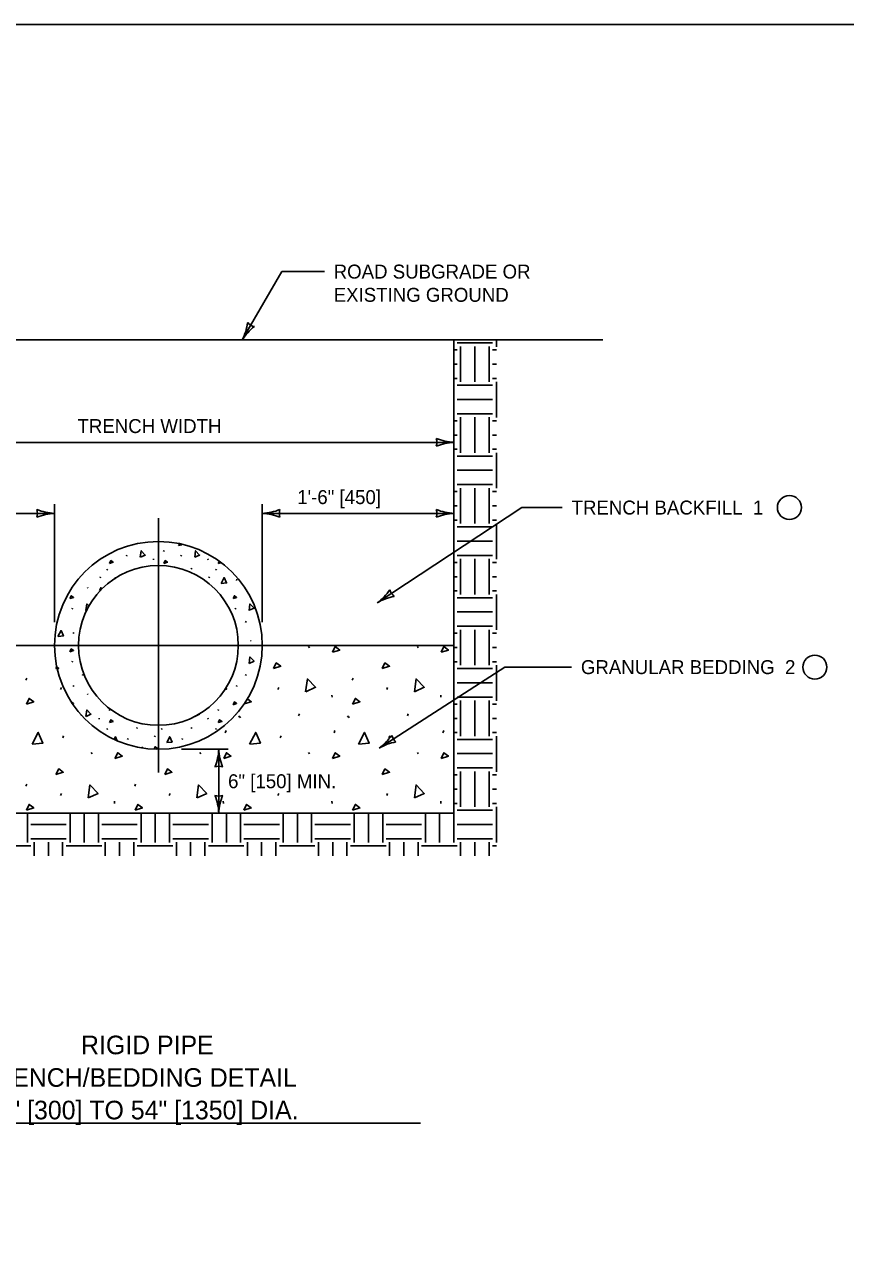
# Model space of a CAD drawing. Extents: x 49991.4 to 50061.4, y 49960.6 to 50011.4.
# Drawn here: x 50001.82 to 50005.35, y 49993.73 to 49999 of the extents above; entities that cross this region are included whole.
import ezdxf

# ---------------------------------------------------------------- set-up
doc = ezdxf.new("R2010")
doc.units = 0
for name, color, linetype in [('Level 1', 7, 'Continuous'), ('Level 2', 7, 'Continuous'), ('Level 3', 7, 'Continuous'), ('Level 5', 7, 'Continuous')]:
    doc.layers.add(name, color=color, linetype=linetype)

msp = doc.modelspace()

# ---------------------------------------------------------------- linework, layer by layer
at = {"layer": 'Level 1'}
for p, q in [((50004.3049, 49997.6424), (50000.4816, 49997.6424)), ((50003.6648, 49997.6424), (50003.6648, 49995.6066)), ((50003.8476, 49997.6424), (50003.8476, 49997.6133)), ((50003.6648, 49997.5991), (50003.6783, 49997.5991)), ((50003.6783, 49997.6297), (50003.8311, 49997.6297)), ((50003.6935, 49997.6144), (50003.6935, 49997.4615)), ((50003.7547, 49997.6144), (50003.7547, 49997.4615)), ((50003.8158, 49997.6144), (50003.8158, 49997.4615)), ((50003.8311, 49997.5991), (50003.8481, 49997.5991)), ((50003.6648, 49997.538), (50003.6783, 49997.538)), ((50003.8311, 49997.538), (50003.8481, 49997.538)), ((50003.6648, 49997.4768), (50003.6783, 49997.4768)), ((50003.6783, 49997.4473), (50003.8311, 49997.4473)), ((50003.8311, 49997.4768), (50003.8481, 49997.4768)), ((50003.8476, 49997.4615), (50003.8476, 49997.3086)), ((50003.6783, 49997.3862), (50003.8311, 49997.3862)), ((50003.6783, 49997.325), (50003.8311, 49997.325)), ((50003.6648, 49997.2944), (50003.6783, 49997.2944)), ((50003.6935, 49997.3097), (50003.6935, 49997.1568)), ((50003.7547, 49997.3097), (50003.7547, 49997.1568)), ((50003.8158, 49997.3097), (50003.8158, 49997.1568)), ((50003.8311, 49997.2944), (50003.8481, 49997.2944)), ((50003.6648, 49997.2333), (50003.6783, 49997.2333)), ((50003.8311, 49997.2333), (50003.8481, 49997.2333)), ((50003.6648, 49997.1721), (50003.6783, 49997.1721)), ((50003.8311, 49997.1721), (50003.8481, 49997.1721)), ((50003.6783, 49997.1426), (50003.8311, 49997.1426)), ((50003.8476, 49997.1568), (50003.8476, 49997.004)), ((50003.6783, 49997.0815), (50003.8311, 49997.0815)), ((50003.6783, 49997.0203), (50003.8311, 49997.0203)), ((50003.6935, 49997.005), (50003.6935, 49996.8521)), ((50003.7547, 49997.005), (50003.7547, 49996.8521)), ((50003.8158, 49997.005), (50003.8158, 49996.8521)), ((50003.6648, 49996.9897), (50003.6783, 49996.9897)), ((50003.8311, 49996.9897), (50003.8481, 49996.9897)), ((50003.6648, 49996.9286), (50003.6783, 49996.9286)), ((50003.8311, 49996.9286), (50003.8481, 49996.9286)), ((50003.6648, 49996.8674), (50003.6783, 49996.8674)), ((50003.8311, 49996.8674), (50003.8481, 49996.8674)), ((50003.8476, 49996.8521), (50003.8476, 49996.6993)), ((50003.6783, 49996.8379), (50003.8311, 49996.8379)), ((50003.6783, 49996.7768), (50003.8311, 49996.7768)), ((50002.256, 49996.7123), (50002.2579, 49996.7167)), ((50002.3721, 49996.7001), (50002.3726, 49996.6957)), ((50002.4157, 49996.7324), (50002.4177, 49996.7368)), ((50002.49, 49996.7123), (50002.4919, 49996.7167)), ((50002.6061, 49996.7001), (50002.6066, 49996.6957)), ((50003.6783, 49996.7156), (50003.8311, 49996.7156)), ((50003.6935, 49996.7003), (50003.6935, 49996.5474)), ((50003.7547, 49996.7003), (50003.7547, 49996.5474)), ((50003.8158, 49996.7003), (50003.8158, 49996.5474)), ((50002.1715, 49996.6557), (50002.1734, 49996.6528)), ((50002.1734, 49996.6546), (50002.1754, 49996.6516)), ((50002.3018, 49996.6588), (50002.3024, 49996.6601)), ((50002.5344, 49996.6557), (50002.5364, 49996.6601)), ((50002.6394, 49996.6557), (50002.6414, 49996.6528)), ((50002.6414, 49996.6546), (50002.6433, 49996.6516)), ((50003.6648, 49996.685), (50003.6783, 49996.685)), ((50003.8311, 49996.685), (50003.8481, 49996.685)), ((50002.1427, 49996.6195), (50002.1446, 49996.6239)), ((50002.6106, 49996.6195), (50002.6125, 49996.6239)), ((50002.7288, 49996.6082), (50002.7307, 49996.6126)), ((50003.6648, 49996.6239), (50003.6783, 49996.6239)), ((50003.8311, 49996.6239), (50003.8481, 49996.6239)), ((50002.088, 49996.577), (50002.0899, 49996.5741)), ((50003.6648, 49996.5627), (50003.6783, 49996.5627)), ((50003.6783, 49996.5332), (50003.8311, 49996.5332)), ((50003.8311, 49996.5627), (50003.8481, 49996.5627)), ((50003.8476, 49996.5474), (50003.8476, 49996.3946)), ((50002.022, 49996.4842), (50002.024, 49996.4886)), ((50002.7239, 49996.4842), (50002.7259, 49996.4886)), ((50002.7684, 49996.4275), (50002.7703, 49996.4319)), ((50003.6783, 49996.4721), (50003.8311, 49996.4721)), ((50002.0269, 49996.3801), (50002.0289, 49996.3845)), ((50002.7305, 49996.3839), (50002.7307, 49996.3845)), ((50003.6648, 49996.3803), (50003.6783, 49996.3803)), ((50003.6783, 49996.4109), (50003.8311, 49996.4109)), ((50003.6935, 49996.3956), (50003.6935, 49996.2427)), ((50003.7547, 49996.3956), (50003.7547, 49996.2427)), ((50003.8158, 49996.3956), (50003.8158, 49996.2427)), ((50003.8311, 49996.3803), (50003.8481, 49996.3803)), ((50001.1217, 49996.3285), (50001.9464, 49996.3285)), ((50002.7898, 49996.3488), (50002.7918, 49996.3459)), ((50002.8401, 49996.3285), (50003.6648, 49996.3285)), ((50003.0395, 49996.3242), (50003.0434, 49996.3183)), ((50003.5074, 49996.3242), (50003.5113, 49996.3183)), ((50003.6648, 49996.3285), (50003.6648, 49995.6066)), ((50003.6648, 49996.3192), (50003.6783, 49996.3192)), ((50003.8311, 49996.3192), (50003.8481, 49996.3192)), ((50001.9525, 49996.2289), (50001.9561, 49996.2364)), ((50001.9573, 49996.2304), (50001.9525, 49996.2289)), ((50002.022, 49996.256), (50002.024, 49996.2604)), ((50003.6648, 49996.258), (50003.6783, 49996.258)), ((50003.6783, 49996.2285), (50003.8311, 49996.2285)), ((50003.8311, 49996.258), (50003.8481, 49996.258)), ((50003.8476, 49996.2427), (50003.8476, 49996.0899)), ((50001.8233, 49996.1786), (50001.8273, 49996.1874)), ((50002.0665, 49996.1994), (50002.0684, 49996.2038)), ((50002.7684, 49996.1994), (50002.7703, 49996.2038)), ((50003.2271, 49996.1786), (50003.231, 49996.1874)), ((50003.6783, 49996.1674), (50003.8311, 49996.1674)), ((50001.9718, 49996.1386), (50001.9757, 49996.1473)), ((50002.0269, 49996.1519), (50002.0289, 49996.1563)), ((50002.088, 49996.1207), (50002.0899, 49996.1178)), ((50002.7288, 49996.1519), (50002.7307, 49996.1563)), ((50002.9077, 49996.1386), (50002.9116, 49996.1473)), ((50003.1399, 49996.114), (50003.1409, 49996.1052)), ((50003.3756, 49996.1386), (50003.3795, 49996.1473)), ((50003.6078, 49996.114), (50003.6088, 49996.1052)), ((50003.6648, 49996.0756), (50003.6783, 49996.0756)), ((50003.6783, 49996.1062), (50003.8311, 49996.1062)), ((50003.6935, 49996.0909), (50003.6935, 49995.9381)), ((50003.7547, 49996.0909), (50003.7547, 49995.9381)), ((50003.8158, 49996.0909), (50003.8158, 49995.9381)), ((50003.8311, 49996.0756), (50003.8481, 49996.0756)), ((50002.0607, 49996.0252), (50002.0622, 49996.0285)), ((50002.1382, 49996.0156), (50002.1386, 49996.0112)), ((50002.1818, 49996.0479), (50002.1837, 49996.0523)), ((50002.6061, 49996.0156), (50002.6066, 49996.0112)), ((50002.6497, 49996.0479), (50002.6516, 49996.0523)), ((50002.7251, 49996.0306), (50002.7259, 49996.0323)), ((50002.7387, 49996.0252), (50002.7426, 49996.0194)), ((50002.7426, 49996.023), (50002.7465, 49996.0172)), ((50002.9965, 49996.0252), (50003.0005, 49996.034)), ((50003.2066, 49996.0252), (50003.2105, 49996.0194)), ((50003.2105, 49996.023), (50003.2144, 49996.0172)), ((50003.4645, 49996.0252), (50003.4684, 49996.034)), ((50003.6648, 49996.0145), (50003.6783, 49996.0145)), ((50003.8311, 49996.0145), (50003.8481, 49996.0145)), ((50002.1715, 49995.9712), (50002.1734, 49995.9683)), ((50002.1734, 49995.9701), (50002.1754, 49995.9672)), ((50002.3004, 49995.9712), (50002.3024, 49995.9756)), ((50002.4055, 49995.9712), (50002.4074, 49995.9683)), ((50002.4074, 49995.9701), (50002.4094, 49995.9672)), ((50002.5344, 49995.9712), (50002.5364, 49995.9756)), ((50002.6394, 49995.9712), (50002.6414, 49995.9683)), ((50002.6414, 49995.9701), (50002.6433, 49995.9672)), ((50002.681, 49995.9528), (50002.6849, 49995.9616)), ((50003.1489, 49995.9528), (50003.1528, 49995.9616)), ((50003.6168, 49995.9528), (50003.6207, 49995.9616)), ((50003.6648, 49995.9533), (50003.6783, 49995.9533)), ((50003.8311, 49995.9533), (50003.8481, 49995.9533)), ((50001.9816, 49995.9304), (50001.9855, 49995.9392)), ((50002.2609, 49995.9238), (50002.2628, 49995.9282)), ((50002.3766, 49995.935), (50002.3786, 49995.9394)), ((50002.4948, 49995.9238), (50002.4968, 49995.9282)), ((50002.9174, 49995.9304), (50002.9213, 49995.9392)), ((50003.3853, 49995.9304), (50003.3892, 49995.9392)), ((50003.6783, 49995.9238), (50003.8311, 49995.9238)), ((50003.8476, 49995.9381), (50003.8476, 49995.7852)), ((50002.1037, 49995.8679), (50002.1076, 49995.862)), ((50002.3219, 49995.8925), (50002.3239, 49995.8896)), ((50002.5716, 49995.8679), (50002.5755, 49995.862)), ((50003.0395, 49995.8679), (50003.0434, 49995.862)), ((50003.5074, 49995.8679), (50003.5113, 49995.862)), ((50003.6783, 49995.8627), (50003.8311, 49995.8627)), ((50003.6783, 49995.8015), (50003.8311, 49995.8015)), ((50003.6648, 49995.771), (50003.6783, 49995.771)), ((50003.6935, 49995.7862), (50003.6935, 49995.6334)), ((50003.7547, 49995.7862), (50003.7547, 49995.6334)), ((50003.8158, 49995.7862), (50003.8158, 49995.6334)), ((50003.8311, 49995.771), (50003.8481, 49995.771)), ((50001.8233, 49995.7223), (50001.8273, 49995.7311)), ((50001.9718, 49995.6823), (50001.9757, 49995.6911)), ((50002.2913, 49995.7223), (50002.2952, 49995.7311)), ((50002.4397, 49995.6823), (50002.4436, 49995.6911)), ((50002.9077, 49995.6823), (50002.9116, 49995.6911)), ((50003.3756, 49995.6823), (50003.3795, 49995.6911)), ((50003.6648, 49995.7098), (50003.6783, 49995.7098)), ((50003.8311, 49995.7098), (50003.8481, 49995.7098)), ((50002.2041, 49995.6577), (50002.205, 49995.6489)), ((50002.672, 49995.6577), (50002.673, 49995.6489)), ((50003.1399, 49995.6577), (50003.1409, 49995.6489)), ((50003.6078, 49995.6577), (50003.6088, 49995.6489)), ((50003.6648, 49995.6486), (50003.6783, 49995.6486)), ((50003.8311, 49995.6486), (50003.8481, 49995.6486)), ((50003.6648, 49995.6066), (50001.1217, 49995.6066)), ((50001.1217, 49995.6066), (50003.6648, 49995.6066)), ((50001.8295, 49995.6066), (50001.8295, 49995.4805)), ((50002.013, 49995.6066), (50002.013, 49995.4805)), ((50002.0741, 49995.6066), (50002.0741, 49995.4805)), ((50002.1353, 49995.6066), (50002.1353, 49995.4805)), ((50002.3187, 49995.6066), (50002.3187, 49995.4805)), ((50002.3799, 49995.6066), (50002.3799, 49995.4805)), ((50002.441, 49995.6066), (50002.441, 49995.4805)), ((50002.6245, 49995.6066), (50002.6245, 49995.4805)), ((50002.6856, 49995.6066), (50002.6856, 49995.4805)), ((50002.7468, 49995.6066), (50002.7468, 49995.4805)), ((50002.9303, 49995.6066), (50002.9303, 49995.4805)), ((50002.9914, 49995.6066), (50002.9914, 49995.4805)), ((50003.0526, 49995.6066), (50003.0526, 49995.4805)), ((50003.236, 49995.6066), (50003.236, 49995.4805)), ((50003.2972, 49995.6066), (50003.2972, 49995.4805)), ((50003.3583, 49995.6066), (50003.3583, 49995.4805)), ((50003.5418, 49995.6066), (50003.5418, 49995.4805)), ((50003.6029, 49995.6066), (50003.6029, 49995.4805)), ((50003.6641, 49995.6066), (50003.6641, 49995.4805)), ((50003.6783, 49995.6191), (50003.8311, 49995.6191)), ((50003.8476, 49995.6334), (50003.8476, 49995.4805)), ((50001.8437, 49995.558), (50001.9965, 49995.558)), ((50002.1494, 49995.558), (50002.3023, 49995.558)), ((50002.4552, 49995.558), (50002.6081, 49995.558)), ((50002.761, 49995.558), (50002.9138, 49995.558)), ((50003.0667, 49995.558), (50003.2196, 49995.558)), ((50003.3725, 49995.558), (50003.5254, 49995.558)), ((50003.6783, 49995.558), (50003.8311, 49995.558)), ((50001.8437, 49995.4968), (50001.9965, 49995.4968)), ((50001.8589, 49995.4815), (50001.8589, 49995.4232)), ((50001.9201, 49995.4815), (50001.9201, 49995.4232)), ((50001.9812, 49995.4815), (50001.9812, 49995.4232)), ((50002.1494, 49995.4968), (50002.3023, 49995.4968)), ((50002.1647, 49995.4815), (50002.1647, 49995.4232)), ((50002.2259, 49995.4815), (50002.2259, 49995.4232)), ((50002.287, 49995.4815), (50002.287, 49995.4232)), ((50002.4552, 49995.4968), (50002.6081, 49995.4968)), ((50002.4705, 49995.4815), (50002.4705, 49995.4232)), ((50002.5316, 49995.4815), (50002.5316, 49995.4232)), ((50002.5928, 49995.4815), (50002.5928, 49995.4232)), ((50002.761, 49995.4968), (50002.9138, 49995.4968)), ((50002.7762, 49995.4815), (50002.7762, 49995.4232)), ((50002.8374, 49995.4815), (50002.8374, 49995.4232)), ((50002.8985, 49995.4815), (50002.8985, 49995.4232)), ((50003.0667, 49995.4968), (50003.2196, 49995.4968)), ((50003.082, 49995.4815), (50003.082, 49995.4232)), ((50003.1432, 49995.4815), (50003.1432, 49995.4232)), ((50003.2043, 49995.4815), (50003.2043, 49995.4232)), ((50003.3725, 49995.4968), (50003.5254, 49995.4968)), ((50003.3878, 49995.4815), (50003.3878, 49995.4232)), ((50003.4489, 49995.4815), (50003.4489, 49995.4232)), ((50003.5101, 49995.4815), (50003.5101, 49995.4232)), ((50003.6783, 49995.4968), (50003.8311, 49995.4968)), ((50003.6935, 49995.4815), (50003.6935, 49995.4232)), ((50003.7547, 49995.4815), (50003.7547, 49995.4232)), ((50003.8158, 49995.4815), (50003.8158, 49995.4232)), ((50001.6908, 49995.4663), (50001.8437, 49995.4663)), ((50001.9965, 49995.4663), (50002.1494, 49995.4663)), ((50002.3023, 49995.4663), (50002.4552, 49995.4663)), ((50002.6081, 49995.4663), (50002.761, 49995.4663)), ((50002.9138, 49995.4663), (50003.0667, 49995.4663)), ((50003.2196, 49995.4663), (50003.3725, 49995.4663)), ((50003.5254, 49995.4663), (50003.6783, 49995.4663)), ((50003.8311, 49995.4663), (50003.8481, 49995.4663))]:
    msp.add_line(p, q, dxfattribs=at)
msp.add_lwpolyline([(49999.3835, 49998.9992), (50016.7501, 49998.9992), (50016.7501, 49987.7988), (49999.3835, 49987.7988)], close=True, dxfattribs=at)
for points in [[(50002.4803, 49996.7575), (50002.4834, 49996.7641)], [(50002.4934, 49996.7616), (50002.4803, 49996.7575)], [(50002.1827, 49996.6811), (50002.1886, 49996.6933), (50002.1984, 49996.686), (50002.1827, 49996.6811)], [(50002.3154, 49996.7073), (50002.3193, 49996.7352), (50002.3368, 49996.7171), (50002.3159, 49996.7074)], [(50002.4167, 49996.6811), (50002.4226, 49996.6933), (50002.4323, 49996.686), (50002.4167, 49996.6811)], [(50002.5494, 49996.7073), (50002.5532, 49996.7352), (50002.5707, 49996.7171), (50002.5498, 49996.7074)], [(50002.6506, 49996.6811), (50002.6542, 49996.6885)], [(50002.6601, 49996.684), (50002.6506, 49996.6811)], [(50002.2051, 49996.6142), (50002.2081, 49996.62), (50002.2093, 49996.6174)], [(50002.6629, 49996.5951), (50002.676, 49996.62), (50002.6863, 49996.597), (50002.6633, 49996.5951)], [(50002.0124, 49996.5294), (50002.0182, 49996.5416), (50002.028, 49996.5343), (50002.0124, 49996.5294)], [(50002.1393, 49996.5643), (50002.1451, 49996.5765), (50002.1514, 49996.5718)], [(50002.1473, 49996.5668), (50002.1393, 49996.5643)], [(50002.7142, 49996.5294), (50002.7201, 49996.5416), (50002.7299, 49996.5343), (50002.7142, 49996.5294)], [(50002.0815, 49996.4791), (50002.0853, 49996.507), (50002.0955, 49996.4966)], [(50002.0884, 49996.4823), (50002.0819, 49996.4793)], [(50002.7833, 49996.4791), (50002.7872, 49996.507), (50002.8047, 49996.489), (50002.7838, 49996.4793)], [(50001.961, 49996.3669), (50001.9742, 49996.3918), (50001.9844, 49996.3689), (50001.9615, 49996.3669)], [(50003.1421, 49996.2988), (50003.1538, 49996.3232), (50003.1733, 49996.3085), (50003.1421, 49996.2988)], [(50003.61, 49996.2988), (50003.6217, 49996.3232), (50003.6413, 49996.3085), (50003.61, 49996.2988)], [(50002.0124, 49996.3012), (50002.0182, 49996.3134), (50002.028, 49996.3061), (50002.0124, 49996.3012)], [(50002.7833, 49996.251), (50002.7872, 49996.2789), (50002.8047, 49996.2608), (50002.7838, 49996.2512)], [(50001.9588, 49996.2339), (50001.9644, 49996.2297), (50001.9601, 49996.2283)], [(50002.8883, 49996.2289), (50002.9, 49996.2533), (50002.9196, 49996.2387), (50002.8883, 49996.2289)], [(50003.3562, 49996.2289), (50003.3679, 49996.2533), (50003.3875, 49996.2387), (50003.3562, 49996.2289)], [(50003.0265, 49996.1284), (50003.0342, 49996.1843), (50003.0692, 49996.1482), (50003.0274, 49996.1288)], [(50003.4944, 49996.1284), (50003.5021, 49996.1843), (50003.5371, 49996.1482), (50003.4953, 49996.1288)], [(50002.6831, 49996.148), (50002.6863, 49996.1407), (50002.678, 49996.14)], [(50001.8253, 49996.076), (50001.837, 49996.1005), (50001.8566, 49996.0858), (50001.8253, 49996.076)], [(50002.0219, 49996.0825), (50002.028, 49996.078), (50002.0259, 49996.0773)], [(50002.7142, 49996.0731), (50002.7201, 49996.0853), (50002.7299, 49996.078), (50002.7142, 49996.0731)], [(50002.776, 49996.0981), (50002.7924, 49996.0858), (50002.7622, 49996.0764)], [(50003.229, 49996.076), (50003.2408, 49996.1005), (50003.2603, 49996.0858), (50003.229, 49996.076)], [(50002.0815, 49996.0228), (50002.0853, 49996.0508), (50002.1028, 49996.0327), (50002.0819, 49996.023)], [(50002.1827, 49995.9966), (50002.1886, 49996.0088), (50002.1984, 49996.0015), (50002.1827, 49995.9966)], [(50002.5494, 49996.0228), (50002.5495, 49996.0241)], [(50002.5682, 49996.0353), (50002.5707, 49996.0327), (50002.5498, 49996.023)], [(50002.6506, 49995.9966), (50002.6565, 49996.0088), (50002.6663, 49996.0015), (50002.6506, 49995.9966)], [(50001.8497, 49995.904), (50001.8761, 49995.9538), (50001.8966, 49995.9079), (50001.8507, 49995.904)], [(50002.7856, 49995.904), (50002.8119, 49995.9538), (50002.8324, 49995.9079), (50002.7865, 49995.904)], [(50003.2535, 49995.904), (50003.2798, 49995.9538), (50003.3004, 49995.9079), (50003.2544, 49995.904)], [(50002.2028, 49995.9254), (50002.2081, 49995.9355), (50002.2157, 49995.9185)], [(50002.4289, 49995.9106), (50002.4421, 49995.9355), (50002.4523, 49995.9126), (50002.4294, 49995.9106)], [(50002.2063, 49995.8425), (50002.218, 49995.8669), (50002.2375, 49995.8522), (50002.2063, 49995.8425)], [(50002.3749, 49995.8834), (50002.3791, 49995.8921), (50002.3888, 49995.8847), (50002.382, 49995.8826)], [(50002.6742, 49995.8425), (50002.6859, 49995.8669), (50002.7054, 49995.8522), (50002.6742, 49995.8425)], [(50003.1421, 49995.8425), (50003.1538, 49995.8669), (50003.1733, 49995.8522), (50003.1421, 49995.8425)], [(50003.61, 49995.8425), (50003.6217, 49995.8669), (50003.6413, 49995.8522), (50003.61, 49995.8425)], [(50001.9525, 49995.7726), (50001.9642, 49995.7971), (50001.9837, 49995.7824), (50001.9525, 49995.7726)], [(50002.4204, 49995.7726), (50002.4321, 49995.7971), (50002.4517, 49995.7824), (50002.4204, 49995.7726)], [(50003.3562, 49995.7726), (50003.3679, 49995.7971), (50003.3875, 49995.7824), (50003.3562, 49995.7726)], [(50002.0907, 49995.6722), (50002.0984, 49995.728), (50002.1334, 49995.6919), (50002.0916, 49995.6725)], [(50002.5586, 49995.6722), (50002.5663, 49995.728), (50002.6013, 49995.6919), (50002.5595, 49995.6725)], [(50003.4944, 49995.6722), (50003.5021, 49995.728), (50003.5371, 49995.6919), (50003.4953, 49995.6725)], [(50001.8253, 49995.6197), (50001.837, 49995.6442), (50001.8566, 49995.6295), (50001.8253, 49995.6197)], [(50002.2932, 49995.6197), (50002.3049, 49995.6442), (50002.3245, 49995.6295), (50002.2932, 49995.6197)], [(50002.7611, 49995.6197), (50002.7729, 49995.6442), (50002.7924, 49995.6295), (50002.7611, 49995.6197)], [(50003.229, 49995.6197), (50003.2408, 49995.6442), (50003.2603, 49995.6295), (50003.229, 49995.6197)]]:
    msp.add_lwpolyline(points, dxfattribs=at)
for radius in [0.4469, 0.3438]:
    msp.add_circle((50002.3932, 49996.3285), radius, dxfattribs=at)
msp.add_arc((50002.3932, 49996.3285), 0.4469, 180, 0, dxfattribs=at)
at = {"layer": 'Level 2'}
msp.add_line((50001.283, 49994.2737), (50003.5203, 49994.2737), dxfattribs=at)
for centre in [(50005.108, 49996.9213), (50005.2176, 49996.2349)]:
    msp.add_circle(centre, 0.0517, dxfattribs=at)
at = {"layer": 'Level 3'}
for p, q in [((50002.7537, 49997.6424), (50002.9239, 49997.9363)), ((50003.1072, 49997.9363), (50002.9239, 49997.9363)), ((50001.1217, 49997.2018), (50003.6648, 49997.2018)), ((50001.9464, 49996.4285), (50001.9464, 49996.9362)), ((50002.8401, 49996.4285), (50002.8401, 49996.9362)), ((50003.3347, 49996.5116), (50003.9573, 49996.9213)), ((50004.1309, 49996.9213), (50003.9573, 49996.9213)), ((50001.1217, 49996.8962), (50001.9464, 49996.8962)), ((50003.6648, 49996.8962), (50002.8401, 49996.8962)), ((50003.3424, 49995.8861), (50003.8834, 49996.2349)), ((50004.1709, 49996.2349), (50003.8834, 49996.2349)), ((50002.4932, 49995.8816), (50002.6929, 49995.8816)), ((50002.6529, 49995.6066), (50002.6529, 49995.8816))]:
    msp.add_line(p, q, dxfattribs=at)
for centre, radius, start, end in [((50002.5466, 49997.749), 0.233, 332.7647, 352.0146), ((50002.9414, 49997.5232), 0.2223, 127.3934, 147.5769), ((50002.818, 49997.7533), 0.0548, 222.0762, 257.7986), ((50003.6739, 49997.424), 0.2223, 247.456, 267.6395), ((50003.5366, 49997.2018), 0.0548, 342.1388, 17.8612), ((50003.6763, 49996.9691), 0.233, 92.8273, 112.0772), ((50001.9555, 49997.1184), 0.2223, 247.456, 267.6395), ((50001.8181, 49996.8962), 0.0548, 342.1388, 17.8612), ((50002.8286, 49997.1289), 0.233, 272.8273, 292.0772), ((50002.9683, 49996.8962), 0.0548, 162.1388, 197.8612), ((50003.6739, 49997.1184), 0.2223, 247.456, 267.6395), ((50003.5366, 49996.8962), 0.0548, 342.1388, 17.8612), ((50001.9579, 49996.6635), 0.233, 92.8273, 112.0772), ((50002.831, 49996.6741), 0.2223, 67.456, 87.6395), ((50003.6763, 49996.6635), 0.233, 92.8273, 112.0772), ((50003.1971, 49996.6997), 0.233, 306.1727, 325.4226), ((50003.4491, 49996.321), 0.2223, 100.8014, 120.9849), ((50003.4418, 49996.5821), 0.0548, 195.4842, 231.2066), ((50003.2066, 49996.0754), 0.233, 305.6416, 324.8914), ((50003.455, 49995.6944), 0.2223, 100.2703, 120.4538), ((50003.4501, 49995.9556), 0.0548, 194.9531, 230.6755), ((50002.4308, 49995.8907), 0.2223, 337.456, 357.6395), ((50002.8856, 49995.8931), 0.233, 182.8273, 202.0772), ((50002.6529, 49995.7534), 0.0548, 72.1388, 107.8612), ((50002.6529, 49995.7348), 0.0548, 252.1388, 287.8612), ((50002.4202, 49995.5951), 0.233, 2.8273, 22.0772), ((50002.875, 49995.5974), 0.2223, 157.456, 177.6395)]:
    msp.add_arc(centre, radius, start, end, dxfattribs=at)
at = {"layer": 'Level 5'}
for p, q in [((50002.3932, 49995.7816), (50002.3932, 49996.8753)), ((50001.8464, 49996.3285), (50002.9401, 49996.3285))]:
    msp.add_line(p, q, dxfattribs=at)

# ---------------------------------------------------------------- texts
at = {"layer": 'Level 2'}
for s, height, p in [('ROAD SUBGRADE OR', 0.06, (50003.1472, 49997.9063)), ('EXISTING GROUND', 0.06, (50003.1472, 49997.8063)), ('TRENCH WIDTH', 0.06, (50002.0449, 49997.2418)), ('1\'-6" [450]', 0.06, (50002.9903, 49996.9362)), ('TRENCH BACKFILL  1', 0.06, (50004.1709, 49996.8913)), ('GRANULAR BEDDING  2', 0.06, (50004.2109, 49996.2049)), ('6" [150] MIN.', 0.06, (50002.6929, 49995.7141)), ('RIGID PIPE', 0.08, (50002.0604, 49994.5697)), ('TRENCH/BEDDING DETAIL', 0.08, (50001.6217, 49994.4297)), ('FOR 12" [300] TO 54" [1350] DIA.', 0.08, (50001.3862, 49994.2897))]:
    msp.add_text(s, height=height, dxfattribs=at).set_placement(p)

doc.saveas('drawing.dxf')
